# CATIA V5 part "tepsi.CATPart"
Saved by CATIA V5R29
Part number: tepsi
Revision: HERHANG?
Definition: B??MEYEN
Nomenclature: tepsi
Source: Unknown
Bounding box of the stored display mesh (mm): x -303 to 303, y -20.6 to 600, z -1003 to 0
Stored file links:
  C:\Users\제5강의실-27\Desktop\가치같이_내작업\tepsi.CATPart
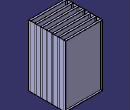
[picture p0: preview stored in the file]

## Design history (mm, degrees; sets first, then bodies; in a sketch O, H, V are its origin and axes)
Body1 "Y?seklik-Ekstr?yon9" (main body)
  Solid1: solid without history
Body2 "D?d?4"
  Solid2: solid without history
Body3 "Aynalama1"
  Solid3: solid without history
Body4 "Aynalama2[1]"
  Solid4: solid without history
Body5 "Aynalama2[2]"
  Solid5: solid without history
